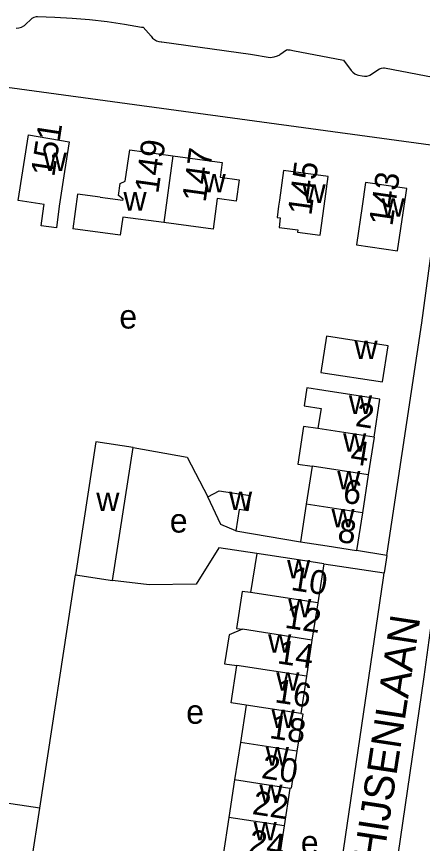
# Model space of a CAD drawing. Extents: x 161093 to 163177, y 379000 to 380904.
# Drawn here: x 162069 to 162136.9, y 380643.6 to 380781.7 of the extents above; entities that cross this region are included whole.
import ezdxf

# ---------------------------------------------------------------- set-up
doc = ezdxf.new("R2010")
doc.units = 0
for name, color, linetype in [('BLT_Basislijn', 7, 'Continuous'), ('BLT_Bebouwing', 7, 'Continuous'), ('BLT_Centroide', 7, 'Continuous'), ('BLT_Huisnummer', 7, 'Continuous'), ('BLT_Huisnummer_ tussenligend', 7, 'Continuous'), ('BLT_Onderverdeling_panden', 7, 'Continuous'), ('BLT_Straatnaam', 7, 'Continuous')]:
    doc.layers.add(name, color=color, linetype=linetype)

msp = doc.modelspace()

# ---------------------------------------------------------------- linework, layer by layer
at = {"layer": 'BLT_Basislijn'}
for p, q in [((162070.33, 380780.18), (162071.61, 380781.39)), ((162090.19, 380779.86), (162091.51, 380778.38)), ((162114.13, 380776.02), (162113.04, 380775.27)), ((162114.36, 380776.1), (162114.13, 380776.02)), ((162128.08, 380771.89), (162129.65, 380772.95)), ((162130.53, 380773.08), (162142.01, 380770.9)), ((162126.18, 380771.88), (162126.77, 380771.74)), ((162130.89, 380691.66), (162125.85, 380692.49)), ((162130.89, 380691.66), (162130.46, 380688.76)), ((162120.35, 380690.27), (162130.46, 380688.76)), ((162072.89, 380649.45), (162078.87, 380688.44)), ((162072.89, 380649.45), (162052.6, 380652.57)), ((162071.52, 380640.48), (162072.89, 380649.45))]:
    msp.add_line(p, q, dxfattribs=at)
for points in [[(162071.61, 380781.39), (162071.96, 380781.55), (162072.33, 380781.64), (162072.5, 380781.66)], [(162072.5, 380781.66), (162075.42, 380781.57), (162078.34, 380781.39), (162081.24, 380781.14), (162084.15, 380780.81), (162087.04, 380780.4), (162089.91, 380779.91), (162090.19, 380779.86)], [(162068.97, 380779.73), (162069.4, 380779.78), (162069.83, 380779.9), (162070.22, 380780.1), (162070.33, 380780.18)], [(162091.51, 380778.38), (162091.76, 380778.06), (162092.06, 380777.8), (162092.41, 380777.61), (162092.79, 380777.49), (162093.19, 380777.45), (162093.32, 380777.45)], [(162093.32, 380777.45), (162108.14, 380775.37), (162111.42, 380774.81)], [(162114.36, 380776.1), (162114.74, 380776.11), (162115.21, 380776.01)], [(162115.21, 380776.01), (162123.63, 380774.39), (162124.94, 380772.64)], [(162111.42, 380774.81), (162112.05, 380774.92), (162112.65, 380775.11), (162113.04, 380775.27)], [(162124.94, 380772.64), (162125.22, 380772.35), (162125.55, 380772.11), (162125.92, 380771.95), (162126.18, 380771.88)], [(162129.65, 380772.95), (162129.99, 380773.06), (162130.34, 380773.1), (162130.53, 380773.08)], [(162140.7, 380759.86), (162051.87, 380771.94)], [(162126.77, 380771.74), (162127.16, 380771.69), (162127.56, 380771.72), (162127.93, 380771.83), (162128.08, 380771.89)], [(162130.89, 380691.66), (162130.95, 380692.04), (162136.73, 380730.54), (162140.7, 380759.86)], [(162088.5, 380709.72), (162097.55, 380708.11), (162100.99, 380701.45)], [(162105.64, 380695.76), (162116.47, 380693.94)], [(162109.16, 380691.98), (162102.83, 380692.92), (162099.06, 380686.88), (162091.2, 380686.77), (162085.08, 380687.47)], [(162121.28, 380626.12), (162130.34, 380687.91), (162130.46, 380688.76)], [(162128.74, 380587.12), (162128.39, 380587.13), (162125.11, 380587.63), (162124.98, 380588.22), (162137.14, 380671.41), (162139.32, 380687.33)]]:
    msp.add_lwpolyline(points, dxfattribs=at)
at = {"layer": 'BLT_Bebouwing'}
for p, q in [((162128.76, 380711.43), (162127.79, 380705.12)), ((162085.08, 380687.47), (162088.5, 380709.72)), ((162118.41, 380706.56), (162117.44, 380700.25)), ((162127.79, 380705.12), (162126.82, 380698.81)), ((162108.07, 380701.69), (162107.68, 380699.12)), ((162106.2, 380699.35), (162105.64, 380695.76)), ((162107.68, 380699.12), (162106.2, 380699.35)), ((162117.44, 380700.25), (162116.47, 380693.94)), ((162126.82, 380698.81), (162125.85, 380692.49)), ((162109.16, 380691.98), (162108.13, 380685.46)), ((162120.35, 380690.27), (162119.34, 380683.74)), ((162078.87, 380688.44), (162085.08, 380687.47)), ((162119.34, 380683.74), (162118.39, 380677.55)), ((162118.39, 380677.55), (162117.47, 380671.54)), ((162117.47, 380671.54), (162116.51, 380665.29)), ((162107.38, 380666.67), (162106.42, 380660.42)), ((162106.42, 380660.42), (162105.46, 380654.18)), ((162105.46, 380654.18), (162104.5, 380647.93)), ((162114.71, 380652.77), (162113.74, 380646.53)), ((162104.5, 380647.93), (162103.54, 380641.68)), ((162113.74, 380646.53), (162112.79, 380640.28))]:
    msp.add_line(p, q, dxfattribs=at)
for points in [[(162077.05, 380755.78), (162076.17, 380750), (162075.69, 380746.4), (162073.16, 380746.73), (162073.6, 380750), (162073.64, 380750.26), (162069.3, 380750.93), (162071, 380761.88), (162077.81, 380760.72), (162077.05, 380755.78)], [(162082.97, 380751.48), (162086.79, 380750.97), (162086.82, 380751.19), (162086.05, 380751.78), (162086.34, 380753.8), (162087.2, 380754.15), (162087.93, 380759.42), (162095.13, 380758.42)], [(162095.13, 380758.42), (162103.37, 380757.27), (162103.03, 380754.83), (162106.2, 380754.39), (162105.71, 380750.84), (162102.56, 380751.28), (162102.38, 380750), (162101.86, 380746.16), (162093.63, 380747.27)], [(162120.4, 380750), (162121.07, 380754.97), (162113.62, 380755.97), (162112.95, 380751.01), (162112.81, 380750), (162112.56, 380748.09), (162113.09, 380748.02), (162112.88, 380746.44), (162116.02, 380746.02), (162115.97, 380745.68), (162119.76, 380745.18), (162120.4, 380750)], [(162133.78, 380750), (162134.21, 380752.97), (162127.34, 380753.96), (162126.77, 380750), (162125.83, 380743.52), (162132.7, 380742.53), (162133.78, 380750)], [(162082.97, 380751.48), (162079.2, 380751.98), (162078.43, 380746.2)], [(162093.63, 380747.27), (162086.78, 380748.18), (162086.36, 380745.14), (162078.43, 380746.2)], [(162120.8, 380728.28), (162119.87, 380722.22), (162130.17, 380720.64), (162131.11, 380726.7), (162120.8, 380728.28)], [(162128.76, 380711.43), (162129.73, 380717.75), (162120.36, 380719.19), (162117.54, 380719.64), (162117.09, 380716.66), (162119.9, 380716.23), (162119.6, 380714.25), (162119.39, 380712.88)], [(162119.39, 380712.88), (162116.99, 380713.18), (162116.05, 380706.94), (162118.41, 380706.56)], [(162088.5, 380709.72), (162082.29, 380710.67), (162078.87, 380688.44)], [(162100.99, 380701.45), (162102.89, 380702.49), (162108.07, 380701.69)], [(162105.64, 380695.76), (162103.18, 380696.85), (162100.99, 380701.45)], [(162116.47, 380693.94), (162120.9, 380693.26), (162125.85, 380692.49)], [(162120.35, 380690.27), (162115.41, 380691.03), (162109.16, 380691.98)], [(162108.13, 380685.46), (162106.73, 380685.68), (162105.78, 380679.49), (162106.79, 380679.34)], [(162106.79, 380679.34), (162104.53, 380678.43), (162103.76, 380673.6), (162105.84, 380673.27)], [(162107.38, 380666.67), (162104.86, 380667.07), (162105.84, 380673.27)], [(162116.51, 380665.29), (162116.84, 380665.25), (162115.88, 380658.99)], [(162115.88, 380658.99), (162114.93, 380652.82), (162114.71, 380652.77)]]:
    msp.add_lwpolyline(points, dxfattribs=at)
at = {"layer": 'BLT_Onderverdeling_panden'}
for p, q in [((162095.13, 380758.42), (162093.63, 380747.27)), ((162128.76, 380711.43), (162119.39, 380712.88)), ((162127.79, 380705.12), (162118.41, 380706.56)), ((162126.82, 380698.81), (162117.44, 380700.25)), ((162119.34, 380683.74), (162108.13, 380685.46)), ((162118.39, 380677.55), (162106.79, 380679.34)), ((162117.47, 380671.54), (162105.84, 380673.27)), ((162116.51, 380665.29), (162107.38, 380666.67)), ((162115.88, 380658.99), (162106.42, 380660.42)), ((162114.71, 380652.77), (162105.46, 380654.18)), ((162113.74, 380646.53), (162104.5, 380647.93))]:
    msp.add_line(p, q, dxfattribs=at)

# ---------------------------------------------------------------- texts
at = {"layer": 'BLT_Centroide'}
for s, p in [('w', (162073.56, 380755.86)), ('w', (162100.11, 380752.28)), ('w', (162116.81, 380750.55)), ('w', (162086.89, 380749.27)), ('w', (162130.02, 380748.23)), ('e', (162086.2, 380729.56)), ('w', (162125.49, 380724.47)), ('w', (162124.56, 380715.31)), ('w', (162123.59, 380709)), ('w', (162122.61, 380702.69)), ('w', (162082.35, 380699.08)), ('w', (162104.53, 380699.25)), ('w', (162121.64, 380696.38)), ('e', (162094.63, 380695.49)), ('w', (162114.23, 380687.84)), ('w', (162114.41, 380681.34)), ('w', (162111.06, 380675.44)), ('w', (162112.42, 380669.09)), ('e', (162097.37, 380663.57)), ('w', (162111.63, 380662.84)), ('w', (162110.67, 380656.59)), ('w', (162109.6, 380650.34)), ('w', (162108.64, 380644.09)), ('e', (162116.52, 380641.75))]:
    msp.add_text(s, height=4, dxfattribs=at).set_placement(p)
at = {"layer": 'BLT_Huisnummer'}
for s, rotation, p in [('151', 81.2971, (162075.32, 380754.79)), ('149', 82.0731, (162092.71, 380751.99)), ('147', 82.0709, (162100.62, 380750.54)), ('145', 82.3675, (162118.28, 380748.34)), ('143', 81.7862, (162131.82, 380746.56)), ('2', 351.2538, (162125.5, 380713.31)), ('8', 351.2556, (162122.51, 380693.97)), ('10', 351.3682, (162114.74, 380685.92)), ('14', 351.3721, (162112.46, 380673.67)), ('18', 351.368, (162111.14, 380661.19)), ('22', 351.2556, (162108.27, 380648.51))]:
    msp.add_text(s, height=4, rotation=rotation, dxfattribs=at).set_placement(p)
at = {"layer": 'BLT_Huisnummer_ tussenligend'}
for s, rotation, p in [('4', 351.2538, (162124.65, 380707.02)), ('6', 351.2538, (162123.39, 380700.52)), ('12', 351.3682, (162113.71, 380679.62)), ('16', 351.3721, (162112.05, 380667.17)), ('20', 351.368, (162109.8, 380654.52)), ('24', 351.2556, (162107.63, 380642.01))]:
    msp.add_text(s, height=4, rotation=rotation, dxfattribs=at).set_placement(p)
at = {"layer": 'BLT_Straatnaam'}
msp.add_text('MATHIJSENLAAN', height=4.9999, rotation=81.3237, dxfattribs=at).set_placement((162128.16, 380626.55))

doc.saveas('drawing.dxf')
